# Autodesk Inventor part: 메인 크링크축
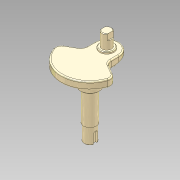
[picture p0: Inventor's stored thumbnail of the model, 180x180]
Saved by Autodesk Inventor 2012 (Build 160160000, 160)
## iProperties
Manager: KYOUNG IL JANG
Company: 한국ATC센터
Created: 2012-10
Part Number: 메인 크링크축
Document SubType Name: Modeling
Density: 1 g/cm^3
Checked By: KYOUNG IL JANG
Vendor: CBT Solutions
Designer: KYOUNG IL JANG
Material: 기본값
크링크폭: 19.000 mm
크랭크길이: 18.000 mm
크랭키위치: 65.000 mm
무게추: 90.000 mm
크랭크각도높이: 21.000 mm
크링크각도: -15.00 deg
Author: KYOUNG IL JANG
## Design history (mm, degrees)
sketch "스케치1"
  geometry: L1 (-19, 109.368)-(-19, 91.368); L2 (-19, 91.368)-(-44.545, 76.619); L3 (19, 109.368)-(19, 91.368); L4 (19, 91.368)-(44.545, 76.619); C1 r 32.5 at (0, 83) reference; C2 r 10 at (0, 83); C3 r 17.5 at (0, 83); A1 r 45 centre (0, 83) between (-44.545, 76.619) and (44.545, 76.619); A2 r 32.5 centre (0, 83) between (-19, 109.368) and (19, 109.368); A3 r 19 centre (0, 109.368) between (19, 109.368) and (-19, 109.368); 1 further point
  constraints: 8 end point, 6 point on circle, 5 centre point, 4 coincident, 2 equal length, 2 vertical alignment, 1 horizontal alignment, 1 parallel, 1 tangent, 1 vertical, 3 other
  dimensions: "d0" = 20 diameter of C2; "d1" = 35 diameter of C3; "d4" = 120 deg angle of L3 L4
  node "참조1"
extrude "돌출1" new body sketch "스케치1" distance "d7" = 12; taper "d8" = 0 deg
extrude "돌출2" join sketch "스케치1" distance "d9" = 5; taper "d10" = 0 deg
extrude "돌출3" join sketch "스케치1" distance "d11" = 100; taper "d12" = 0 deg
sketch "스케치2"
  geometry: C1 r 7.5 at (0, 109.368); C2 r 11 at (0, 109.368); A1 r 19 centre (0, 109.368) between (19, 109.368) and (-19, 109.368) reference; 1 further point
  constraints: 2 centre point, 2 coincident
  dimensions: "d13" = 15 diameter of C1; "d14" = 22 diameter of C2
extrude "돌출4" join sketch "스케치2" distance "d15" = 3; taper "d16" = 0 deg
extrude "돌출5" join sketch "스케치2" distance "d17" = 25; taper "d18" = 0 deg
node "작업 평면1"
sketch "스케치3"
  geometry: L1 (-5.75, 4.815)-(-5.75, -4.815); L2 (5.75, 4.815)-(5.75, -4.815); A1 r 7.5 centre (0, 0) between (-5.75, 4.815) and (-5.75, -4.815) reference; 1 further point
  constraints: 4 end point, 4 point on circle, 2 parallel, 1 vertical
  dimensions: "d20" = 11.5 distance between parallel lines of L2 L1
extrude "돌출6" cut sketch "스케치3" stored distance "d21" = 10; taper "d22" = 0 deg
sketch "스케치4"
  geometry: L1 (-19, 91.368)-(-19, 109.368) reference; L2 (19, 109.368)-(19, 91.368) reference; C1 r 17.5 at (0, 83) reference; 3 further points
  constraints: 2 point on line, 1 horizontal alignment, 1 other
node "작업 평면2"
  node "작업축1"
sketch "스케치5"
  geometry: L1 (0, 0)-(38, 0); L2 (38, 0)-(38, 50); L3 (38, 50)-(0, 50); L4 (0, 50)-(0, 0); L5 (38, 5.185)-(38, -12.202) reference; 2 further points
  constraints: 8 end point, 1 coincident, 1 collinear, 1 horizontal, 1 perpendicular
  dimensions: "d27" = 50 distance between parallel lines of L3 L1
extrude "돌출7" cut sketch "스케치5" stored distance "d28" = 10; taper "d29" = 0 deg
fillet "모깎기1" dims "d23" = 10, "d24" = 2
sketch "스케치6"
  geometry: C1 r 17.5 at (0, 0) reference; C2 r 15 at (0, 0); 1 further point
  constraints: 1 centre point, 1 coincident
  dimensions: "d30" = 30 diameter of C2
extrude "돌출8" join sketch "스케치6" distance "d31" = 21; taper "d32" = 0 deg
sketch "스케치7"
  geometry: C1 r 10 at (0, 0) reference; C2 r 9 at (0, 0); 1 further point
  constraints: 1 centre point, 1 coincident
  dimensions: "d33" = 1 radial gap between concentric circles of C1 C2
extrude "돌출9" cut sketch "스케치7" distance "d34" = 25; taper "d35" = 0 deg
node "작업 평면3"
sketch "스케치8"
  geometry: L1 (-9, 0)-(9, 0) reference; L2 (-3, 0)-(-3, 15); L3 (3, 15)-(3, 0); A1 r 3 centre (0, 15) between (3, 15) and (-3, 15); 2 further points
  constraints: 4 end point, 2 perpendicular, 2 point on circle, 2 point on line, 2 tangent, 1 centre point, 1 midpoint, 1 vertical alignment
  dimensions: "d36" = 6 distance between parallel lines of L3 L2; "d37" = 18 dimension on A1 L1
extrude "돌출10" cut sketch "스케치8" distance "d38" = 3.5; taper "d39" = 0 deg
chamfer "모따기1" distance "d40" = 1; stored, may be unused: second distance "d41" = 2, angle "d42" = 45 deg
node "솔리드1"
node "투영된 루프1"
other parameters: "d19" = 13
